(* Logix 5000 project; controller R21 vendor 1 type 14 code 96 rev 21.11; software revision 21.00; part 4 of 5 *)

ADD_ON_INSTRUCTION PSDNP3EventG30V03   (* revision 1.0, vendor ProSoft Technology Inc *)
VAR_IN_OUT
   EventBuffer : PSDNP3MasterEvent[1]; {required}
END_VAR
VAR_INPUT
   BufferSize : DINT; {required}
   CurrentBufferIndex : DINT; {required}
   Reset : BOOL; {required}
   OutstationNodeAddress : INT; {required}
   OutstationIPAddress0 : INT; {required}
   OutstationIPAddress1 : INT; {required}
   OutstationIPAddress2 : INT; {required}
   OutstationIPAddress3 : INT; {required}
END_VAR
VAR_IN_OUT
   DNP3StaticObject : DINT[1]; {required}
END_VAR
VAR_INPUT
   MaxtElementCount : DINT; {required}
END_VAR
VAR_OUTPUT
   EventsProcessed : DINT; {access Read Only, visible}
   LastElementIndex : DINT; {access Read Only, visible}
   LastValue : DINT; {access Read Only, visible}
   LastStatus : SINT; {access Read Only, visible}
   CurrentUnloadIndex : DINT; {access Read Only, visible}
END_VAR
VAR
   UnloadIndex : DINT; {access None}
   EnableInTemp : BOOL; {access None}
   InitialScan : BOOL; {access None}
   EntryValidForProcessing : BOOL; {access None}
   ElementIndex : DINT; {access None}
   NextIndex : DINT; {access None}
   ResetPulse : BOOL; {access None}
   ResetONS : BOOL; {access None}
END_VAR

ROUTINE Logic   (* ladder *)
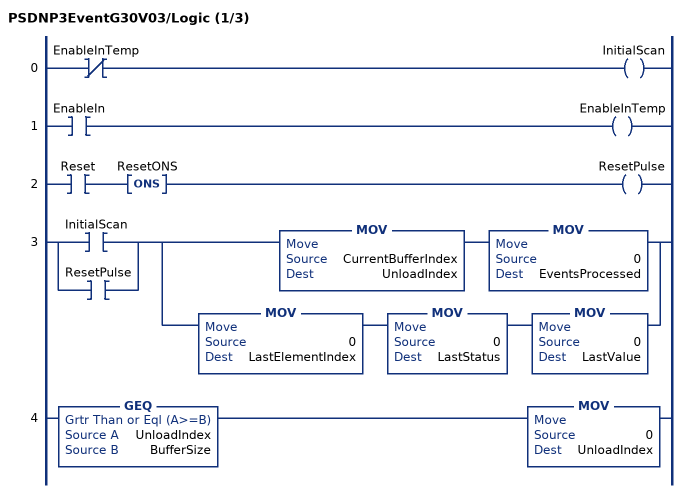
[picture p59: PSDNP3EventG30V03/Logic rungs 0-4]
   0: XIO(EnableInTemp)OTE(InitialScan);
   1: XIC(EnableIn)OTE(EnableInTemp);
   2: XIC(Reset)ONS(ResetONS)OTE(ResetPulse);
   3: [XIC(InitialScan) ,XIC(ResetPulse) ][MOV(CurrentBufferIndex,UnloadIndex) MOV(0,EventsProcessed) ,MOV(0,LastElementIndex) MOV(0,LastStatus) MOV(0,LastValue) ];
   4: GEQ(UnloadIndex,BufferSize)MOV(0,UnloadIndex);
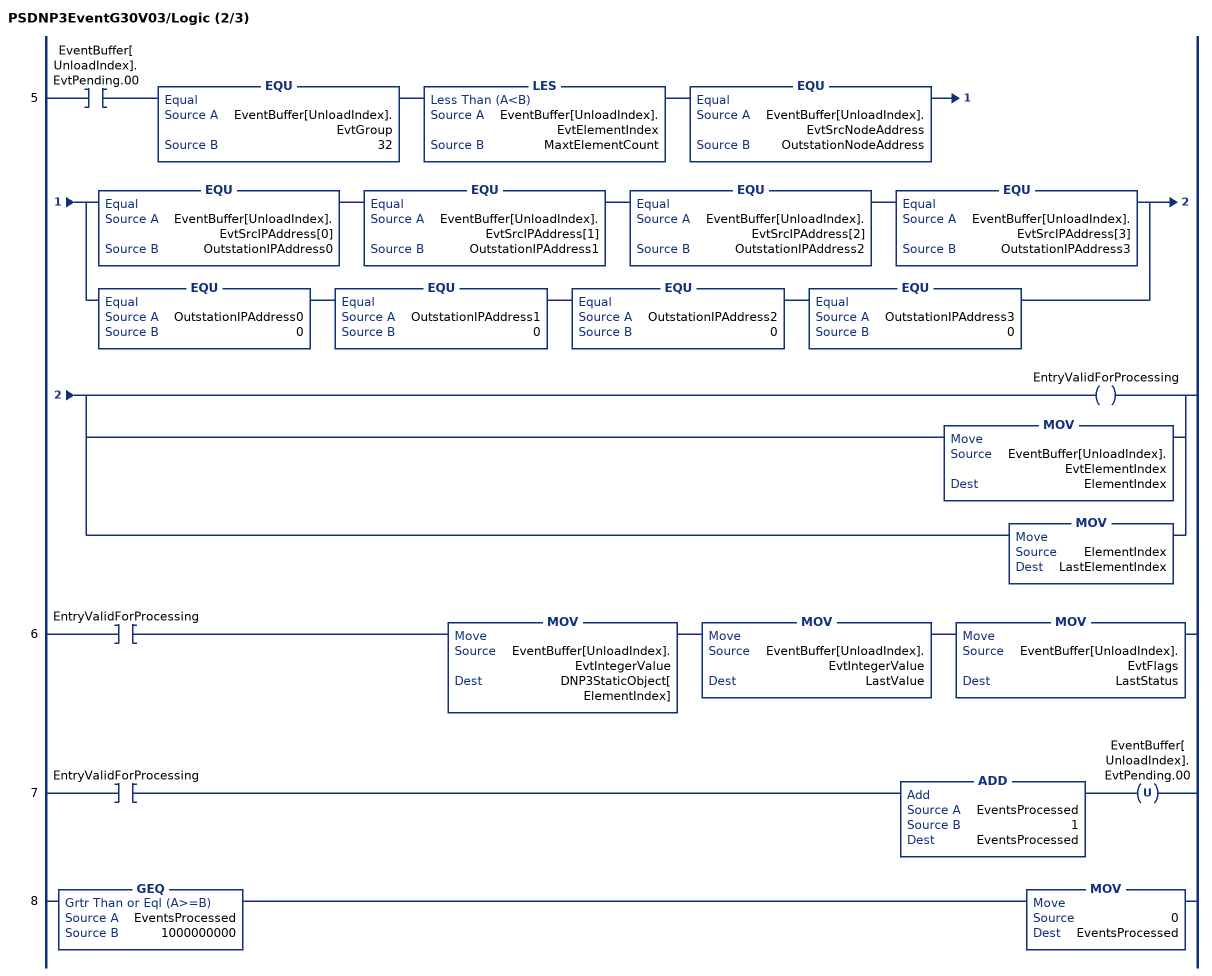
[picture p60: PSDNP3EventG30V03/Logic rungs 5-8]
   5: XIC(EventBuffer[UnloadIndex].EvtPending.00)EQU(EventBuffer[UnloadIndex].EvtGroup,32)LES(EventBuffer[UnloadIndex].EvtElementIndex,MaxtElementCount)EQU(EventBuffer[UnloadIndex].EvtSrcNodeAddress,OutstationNodeAddress)[EQU(EventBuffer[UnloadIndex].EvtSrcIPAddress[0],OutstationIPAddress0) EQU(EventBuffer[UnloadIndex].EvtSrcIPAddress[1],OutstationIPAddress1) EQU(EventBuffer[UnloadIndex].EvtSrcIPAddress[2],OutstationIPAddress2) EQU(EventBuffer[UnloadIndex].EvtSrcIPAddress[3],OutstationIPAddress3) ,EQU(OutstationIPAddress0,0) EQU(OutstationIPAddress1,0) EQU(OutstationIPAddress2,0) EQU(OutstationIPAddress3,0) ][OTE(EntryValidForProcessing) ,MOV(EventBuffer[UnloadIndex].EvtElementIndex,ElementIndex) ,MOV(ElementIndex,LastElementIndex) ];
   6: XIC(EntryValidForProcessing)MOV(EventBuffer[UnloadIndex].EvtIntegerValue,DNP3StaticObject[ElementIndex])MOV(EventBuffer[UnloadIndex].EvtIntegerValue,LastValue)MOV(EventBuffer[UnloadIndex].EvtFlags,LastStatus);
   7: XIC(EntryValidForProcessing)ADD(EventsProcessed,1,EventsProcessed)OTU(EventBuffer[UnloadIndex].EvtPending.00);
   8: GEQ(EventsProcessed,1000000000)MOV(0,EventsProcessed);
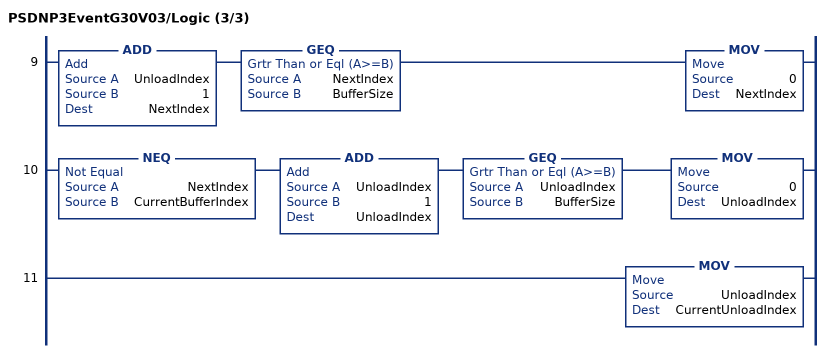
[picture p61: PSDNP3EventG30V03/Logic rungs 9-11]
   9: ADD(UnloadIndex,1,NextIndex)GEQ(NextIndex,BufferSize)MOV(0,NextIndex);
   10: NEQ(NextIndex,CurrentBufferIndex)ADD(UnloadIndex,1,UnloadIndex)GEQ(UnloadIndex,BufferSize)MOV(0,UnloadIndex);
   11: MOV(UnloadIndex,CurrentUnloadIndex);
END_ROUTINE
END_ADD_ON_INSTRUCTION

ADD_ON_INSTRUCTION PSDNP3EventG30V04   (* revision 1.0, vendor ProSoft Technology Inc *)
VAR_IN_OUT
   EventBuffer : PSDNP3MasterEvent[1]; {required}
END_VAR
VAR_INPUT
   BufferSize : DINT; {required}
   CurrentBufferIndex : DINT; {required}
   Reset : BOOL; {required}
   OutstationNodeAddress : INT; {required}
   OutstationIPAddress0 : INT; {required}
   OutstationIPAddress1 : INT; {required}
   OutstationIPAddress2 : INT; {required}
   OutstationIPAddress3 : INT; {required}
END_VAR
VAR_IN_OUT
   DNP3StaticObject : INT[1]; {required}
END_VAR
VAR_INPUT
   MaxtElementCount : DINT; {required}
END_VAR
VAR_OUTPUT
   EventsProcessed : DINT; {access Read Only, visible}
   LastElementIndex : DINT; {access Read Only, visible}
   LastValue : DINT; {access Read Only, visible}
   LastStatus : SINT; {access Read Only, visible}
   CurrentUnloadIndex : DINT; {access Read Only, visible}
END_VAR
VAR
   UnloadIndex : DINT; {access None}
   EnableInTemp : BOOL; {access None}
   InitialScan : BOOL; {access None}
   EntryValidForProcessing : BOOL; {access None}
   ElementIndex : DINT; {access None}
   NextIndex : DINT; {access None}
   ResetPulse : BOOL; {access None}
   ResetONS : BOOL; {access None}
END_VAR

ROUTINE Logic   (* ladder *)
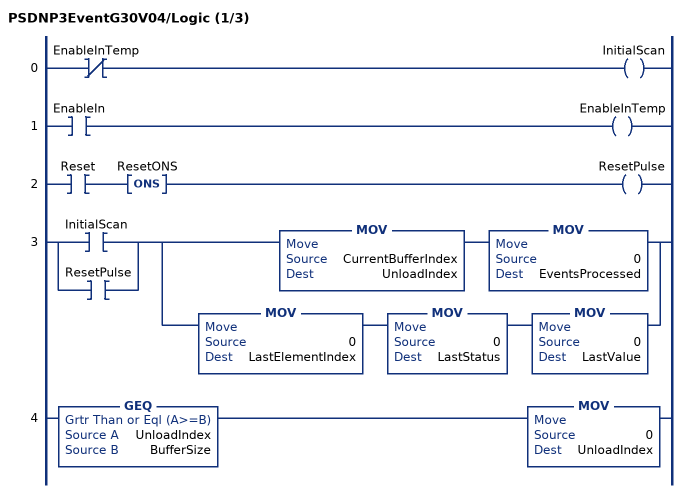
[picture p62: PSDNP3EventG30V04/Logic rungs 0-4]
   0: XIO(EnableInTemp)OTE(InitialScan);
   1: XIC(EnableIn)OTE(EnableInTemp);
   2: XIC(Reset)ONS(ResetONS)OTE(ResetPulse);
   3: [XIC(InitialScan) ,XIC(ResetPulse) ][MOV(CurrentBufferIndex,UnloadIndex) MOV(0,EventsProcessed) ,MOV(0,LastElementIndex) MOV(0,LastStatus) MOV(0,LastValue) ];
   4: GEQ(UnloadIndex,BufferSize)MOV(0,UnloadIndex);
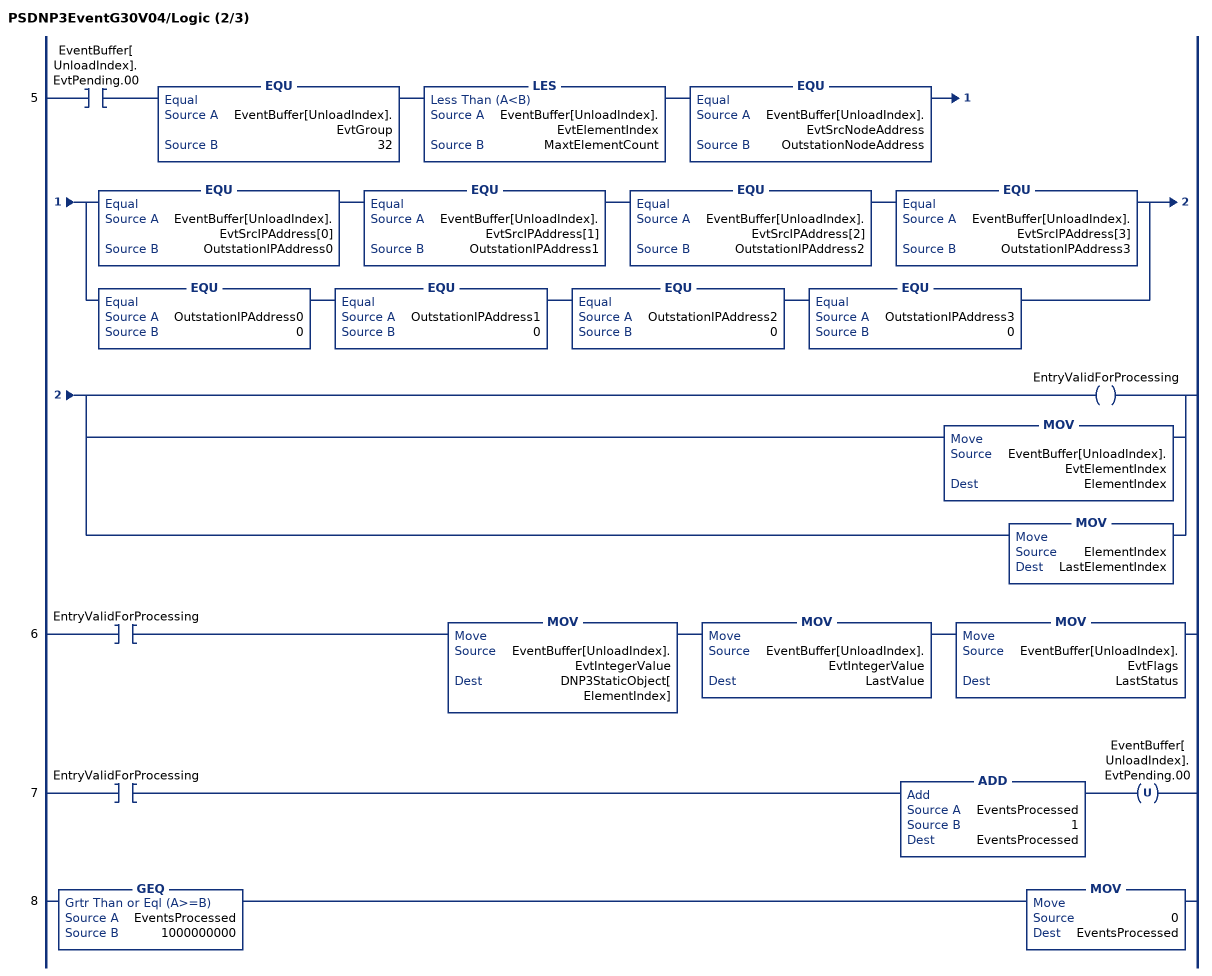
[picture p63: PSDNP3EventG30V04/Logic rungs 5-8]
   5: XIC(EventBuffer[UnloadIndex].EvtPending.00)EQU(EventBuffer[UnloadIndex].EvtGroup,32)LES(EventBuffer[UnloadIndex].EvtElementIndex,MaxtElementCount)EQU(EventBuffer[UnloadIndex].EvtSrcNodeAddress,OutstationNodeAddress)[EQU(EventBuffer[UnloadIndex].EvtSrcIPAddress[0],OutstationIPAddress0) EQU(EventBuffer[UnloadIndex].EvtSrcIPAddress[1],OutstationIPAddress1) EQU(EventBuffer[UnloadIndex].EvtSrcIPAddress[2],OutstationIPAddress2) EQU(EventBuffer[UnloadIndex].EvtSrcIPAddress[3],OutstationIPAddress3) ,EQU(OutstationIPAddress0,0) EQU(OutstationIPAddress1,0) EQU(OutstationIPAddress2,0) EQU(OutstationIPAddress3,0) ][OTE(EntryValidForProcessing) ,MOV(EventBuffer[UnloadIndex].EvtElementIndex,ElementIndex) ,MOV(ElementIndex,LastElementIndex) ];
   6: XIC(EntryValidForProcessing)MOV(EventBuffer[UnloadIndex].EvtIntegerValue,DNP3StaticObject[ElementIndex])MOV(EventBuffer[UnloadIndex].EvtIntegerValue,LastValue)MOV(EventBuffer[UnloadIndex].EvtFlags,LastStatus);
   7: XIC(EntryValidForProcessing)ADD(EventsProcessed,1,EventsProcessed)OTU(EventBuffer[UnloadIndex].EvtPending.00);
   8: GEQ(EventsProcessed,1000000000)MOV(0,EventsProcessed);
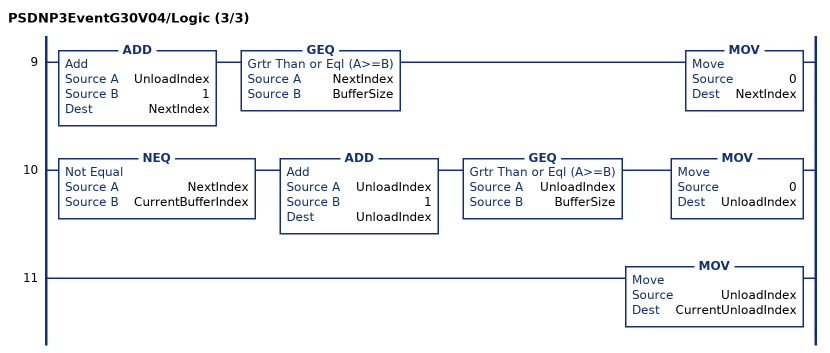
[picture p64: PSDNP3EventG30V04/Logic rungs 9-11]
   9: ADD(UnloadIndex,1,NextIndex)GEQ(NextIndex,BufferSize)MOV(0,NextIndex);
   10: NEQ(NextIndex,CurrentBufferIndex)ADD(UnloadIndex,1,UnloadIndex)GEQ(UnloadIndex,BufferSize)MOV(0,UnloadIndex);
   11: MOV(UnloadIndex,CurrentUnloadIndex);
END_ROUTINE
END_ADD_ON_INSTRUCTION

ADD_ON_INSTRUCTION PSDNP3EventG30V05   (* revision 1.0, vendor ProSoft Technology Inc *)
VAR_IN_OUT
   EventBuffer : PSDNP3MasterEvent[1]; {required}
END_VAR
VAR_INPUT
   BufferSize : DINT; {required}
   CurrentBufferIndex : DINT; {required}
   Reset : BOOL; {required}
   OutstationNodeAddress : INT; {required}
   OutstationIPAddress0 : INT; {required}
   OutstationIPAddress1 : INT; {required}
   OutstationIPAddress2 : INT; {required}
   OutstationIPAddress3 : INT; {required}
END_VAR
VAR_IN_OUT
   DNP3StaticObject : PSDNP3AnalogInputRealFlag[1]; {required}
END_VAR
VAR_INPUT
   MaxtElementCount : DINT; {required}
END_VAR
VAR_OUTPUT
   EventsProcessed : DINT; {access Read Only, visible}
   LastElementIndex : DINT; {access Read Only, visible}
   LastValue : REAL; {access Read Only, visible}
   LastStatus : SINT; {access Read Only, visible}
   CurrentUnloadIndex : DINT; {access Read Only, visible}
END_VAR
VAR
   UnloadIndex : DINT; {access None}
   EnableInTemp : BOOL; {access None}
   InitialScan : BOOL; {access None}
   EntryValidForProcessing : BOOL; {access None}
   ElementIndex : DINT; {access None}
   NextIndex : DINT; {access None}
   ResetPulse : BOOL; {access None}
   ResetONS : BOOL; {access None}
END_VAR

ROUTINE Logic   (* ladder *)
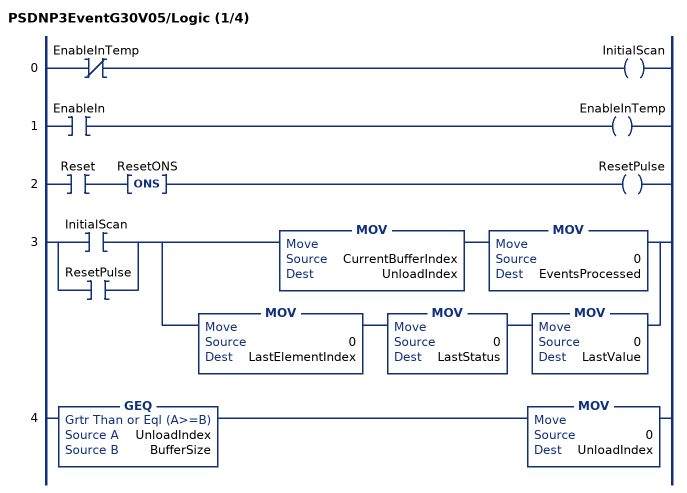
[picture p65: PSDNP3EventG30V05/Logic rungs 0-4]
   0: XIO(EnableInTemp)OTE(InitialScan);
   1: XIC(EnableIn)OTE(EnableInTemp);
   2: XIC(Reset)ONS(ResetONS)OTE(ResetPulse);
   3: [XIC(InitialScan) ,XIC(ResetPulse) ][MOV(CurrentBufferIndex,UnloadIndex) MOV(0,EventsProcessed) ,MOV(0,LastElementIndex) MOV(0,LastStatus) MOV(0,LastValue) ];
   4: GEQ(UnloadIndex,BufferSize)MOV(0,UnloadIndex);
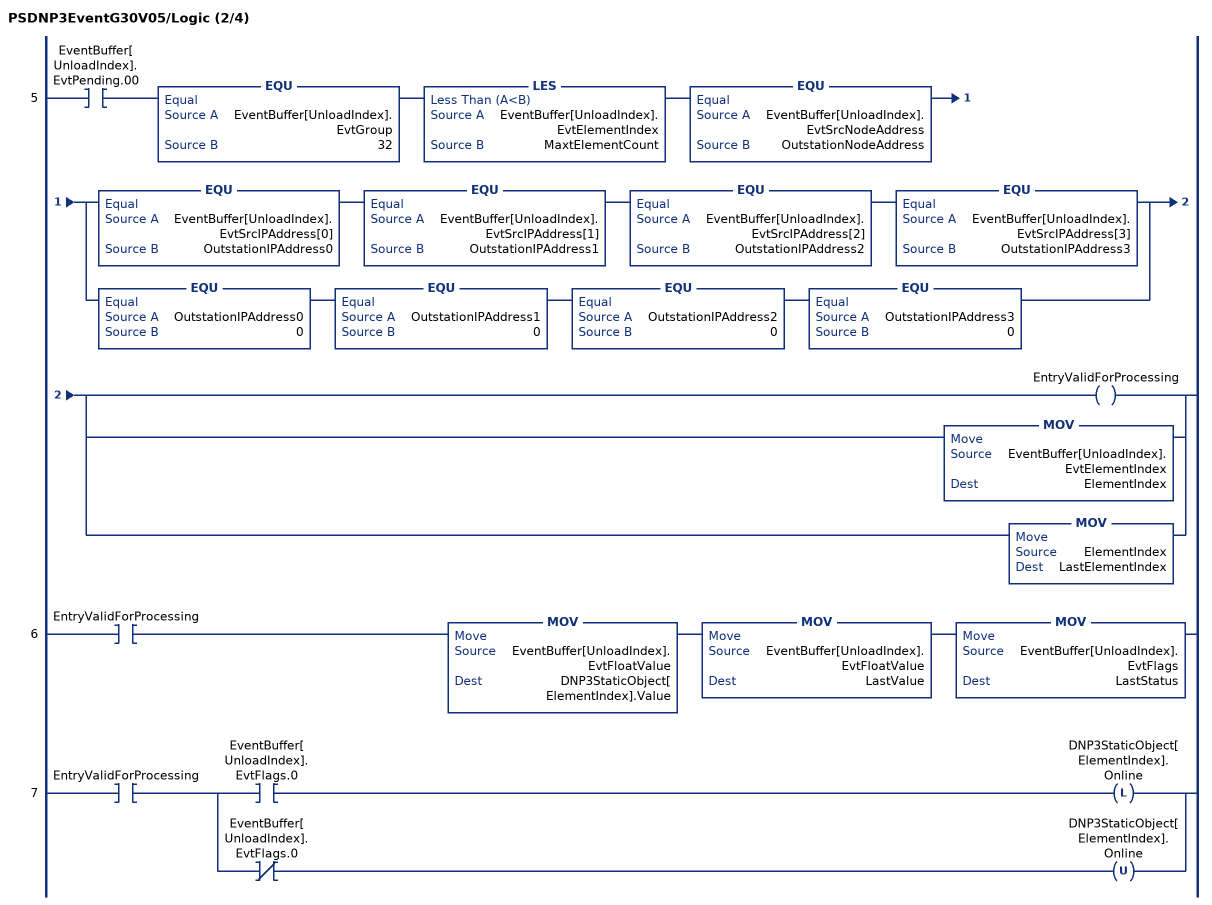
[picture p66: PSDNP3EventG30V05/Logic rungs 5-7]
   5: XIC(EventBuffer[UnloadIndex].EvtPending.00)EQU(EventBuffer[UnloadIndex].EvtGroup,32)LES(EventBuffer[UnloadIndex].EvtElementIndex,MaxtElementCount)EQU(EventBuffer[UnloadIndex].EvtSrcNodeAddress,OutstationNodeAddress)[EQU(EventBuffer[UnloadIndex].EvtSrcIPAddress[0],OutstationIPAddress0) EQU(EventBuffer[UnloadIndex].EvtSrcIPAddress[1],OutstationIPAddress1) EQU(EventBuffer[UnloadIndex].EvtSrcIPAddress[2],OutstationIPAddress2) EQU(EventBuffer[UnloadIndex].EvtSrcIPAddress[3],OutstationIPAddress3) ,EQU(OutstationIPAddress0,0) EQU(OutstationIPAddress1,0) EQU(OutstationIPAddress2,0) EQU(OutstationIPAddress3,0) ][OTE(EntryValidForProcessing) ,MOV(EventBuffer[UnloadIndex].EvtElementIndex,ElementIndex) ,MOV(ElementIndex,LastElementIndex) ];
   6: XIC(EntryValidForProcessing)MOV(EventBuffer[UnloadIndex].EvtFloatValue,DNP3StaticObject[ElementIndex].Value)MOV(EventBuffer[UnloadIndex].EvtFloatValue,LastValue)MOV(EventBuffer[UnloadIndex].EvtFlags,LastStatus);
   7: XIC(EntryValidForProcessing)[XIC(EventBuffer[UnloadIndex].EvtFlags.0) OTL(DNP3StaticObject[ElementIndex].Online) ,XIO(EventBuffer[UnloadIndex].EvtFlags.0) OTU(DNP3StaticObject[ElementIndex].Online) ];
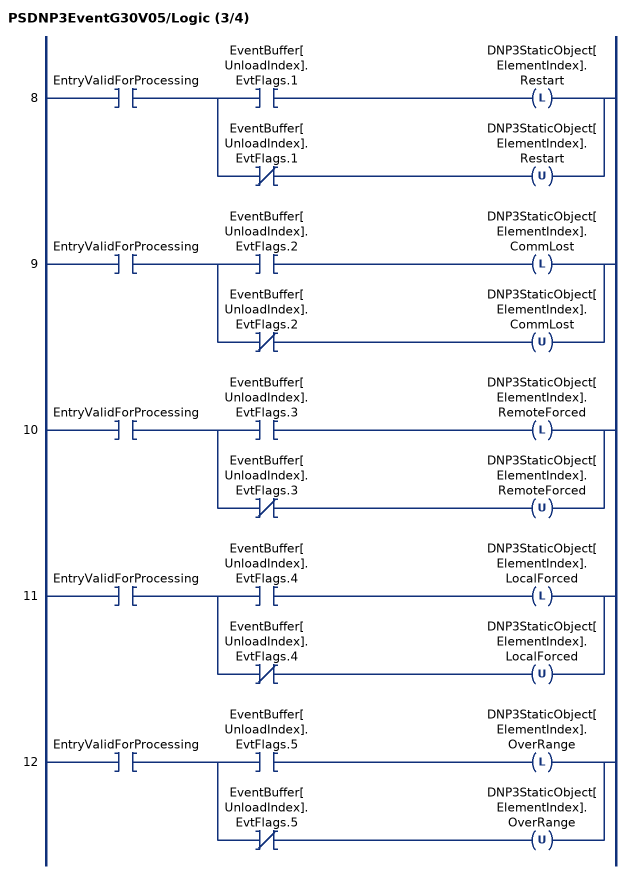
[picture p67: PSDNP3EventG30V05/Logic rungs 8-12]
   8: XIC(EntryValidForProcessing)[XIC(EventBuffer[UnloadIndex].EvtFlags.1) OTL(DNP3StaticObject[ElementIndex].Restart) ,XIO(EventBuffer[UnloadIndex].EvtFlags.1) OTU(DNP3StaticObject[ElementIndex].Restart) ];
   9: XIC(EntryValidForProcessing)[XIC(EventBuffer[UnloadIndex].EvtFlags.2) OTL(DNP3StaticObject[ElementIndex].CommLost) ,XIO(EventBuffer[UnloadIndex].EvtFlags.2) OTU(DNP3StaticObject[ElementIndex].CommLost) ];
   10: XIC(EntryValidForProcessing)[XIC(EventBuffer[UnloadIndex].EvtFlags.3) OTL(DNP3StaticObject[ElementIndex].RemoteForced) ,XIO(EventBuffer[UnloadIndex].EvtFlags.3) OTU(DNP3StaticObject[ElementIndex].RemoteForced) ];
   11: XIC(EntryValidForProcessing)[XIC(EventBuffer[UnloadIndex].EvtFlags.4) OTL(DNP3StaticObject[ElementIndex].LocalForced) ,XIO(EventBuffer[UnloadIndex].EvtFlags.4) OTU(DNP3StaticObject[ElementIndex].LocalForced) ];
   12: XIC(EntryValidForProcessing)[XIC(EventBuffer[UnloadIndex].EvtFlags.5) OTL(DNP3StaticObject[ElementIndex].OverRange) ,XIO(EventBuffer[UnloadIndex].EvtFlags.5) OTU(DNP3StaticObject[ElementIndex].OverRange) ];
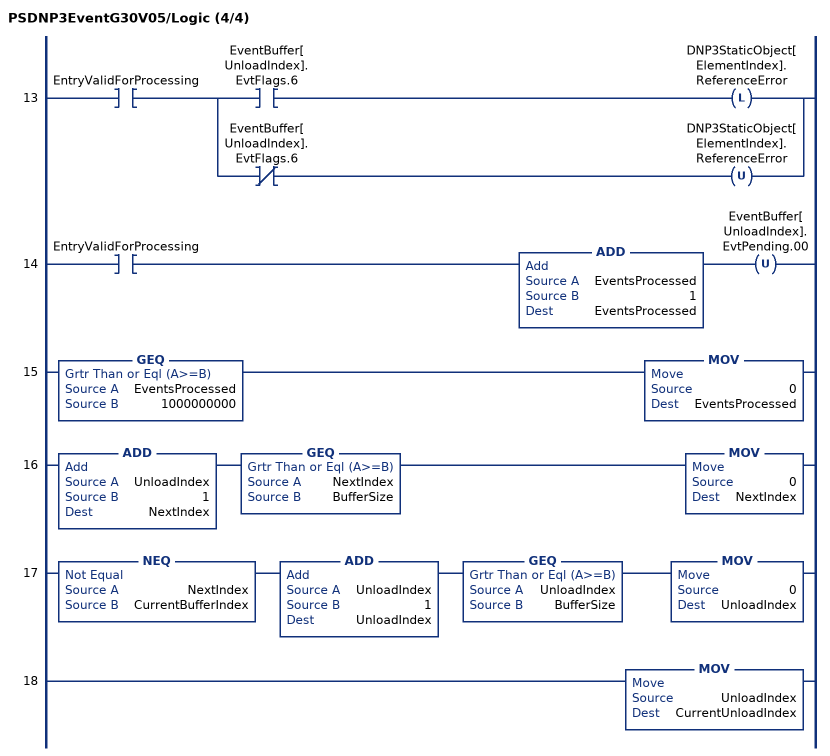
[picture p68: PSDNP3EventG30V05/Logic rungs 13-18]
   13: XIC(EntryValidForProcessing)[XIC(EventBuffer[UnloadIndex].EvtFlags.6) OTL(DNP3StaticObject[ElementIndex].ReferenceError) ,XIO(EventBuffer[UnloadIndex].EvtFlags.6) OTU(DNP3StaticObject[ElementIndex].ReferenceError) ];
   14: XIC(EntryValidForProcessing)ADD(EventsProcessed,1,EventsProcessed)OTU(EventBuffer[UnloadIndex].EvtPending.00);
   15: GEQ(EventsProcessed,1000000000)MOV(0,EventsProcessed);
   16: ADD(UnloadIndex,1,NextIndex)GEQ(NextIndex,BufferSize)MOV(0,NextIndex);
   17: NEQ(NextIndex,CurrentBufferIndex)ADD(UnloadIndex,1,UnloadIndex)GEQ(UnloadIndex,BufferSize)MOV(0,UnloadIndex);
   18: MOV(UnloadIndex,CurrentUnloadIndex);
END_ROUTINE
END_ADD_ON_INSTRUCTION

ADD_ON_INSTRUCTION PSDNP3EventG40V01   (* revision 1.0, vendor ProSoft Technology Inc *)
VAR_IN_OUT
   EventBuffer : PSDNP3MasterEvent[1]; {required}
END_VAR
VAR_INPUT
   BufferSize : DINT; {required}
   CurrentBufferIndex : DINT; {required}
   Reset : BOOL; {required}
   OutstationNodeAddress : INT; {required}
   OutstationIPAddress0 : INT; {required}
   OutstationIPAddress1 : INT; {required}
   OutstationIPAddress2 : INT; {required}
   OutstationIPAddress3 : INT; {required}
END_VAR
VAR_IN_OUT
   DNP3StaticObject : PSDNP3AnalogOutputStatus32Flag[1]; {required}
END_VAR
VAR_INPUT
   MaxtElementCount : DINT; {required}
END_VAR
VAR_OUTPUT
   EventsProcessed : DINT; {access Read Only, visible}
   LastElementIndex : DINT; {access Read Only, visible}
   LastValue : DINT; {access Read Only, visible}
   LastStatus : SINT; {access Read Only, visible}
   CurrentUnloadIndex : DINT; {access Read Only, visible}
END_VAR
VAR
   UnloadIndex : DINT; {access None}
   EnableInTemp : BOOL; {access None}
   InitialScan : BOOL; {access None}
   EntryValidForProcessing : BOOL; {access None}
   ElementIndex : DINT; {access None}
   NextIndex : DINT; {access None}
   ResetPulse : BOOL; {access None}
   ResetONS : BOOL; {access None}
END_VAR

ROUTINE Logic   (* ladder *)
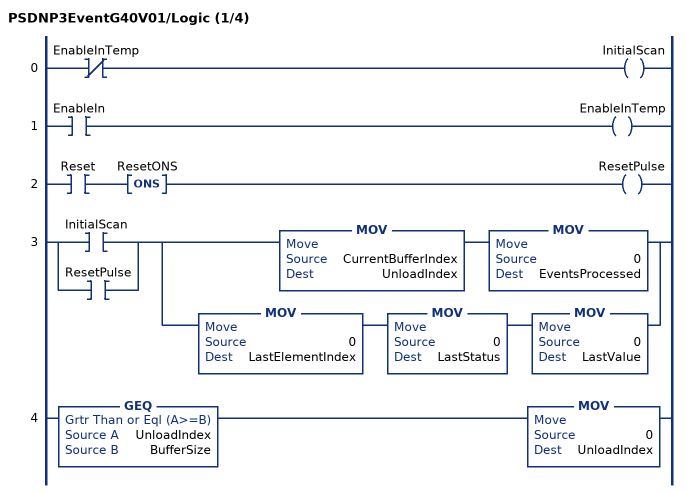
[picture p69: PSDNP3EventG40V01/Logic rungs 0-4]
   0: XIO(EnableInTemp)OTE(InitialScan);
   1: XIC(EnableIn)OTE(EnableInTemp);
   2: XIC(Reset)ONS(ResetONS)OTE(ResetPulse);
   3: [XIC(InitialScan) ,XIC(ResetPulse) ][MOV(CurrentBufferIndex,UnloadIndex) MOV(0,EventsProcessed) ,MOV(0,LastElementIndex) MOV(0,LastStatus) MOV(0,LastValue) ];
   4: GEQ(UnloadIndex,BufferSize)MOV(0,UnloadIndex);
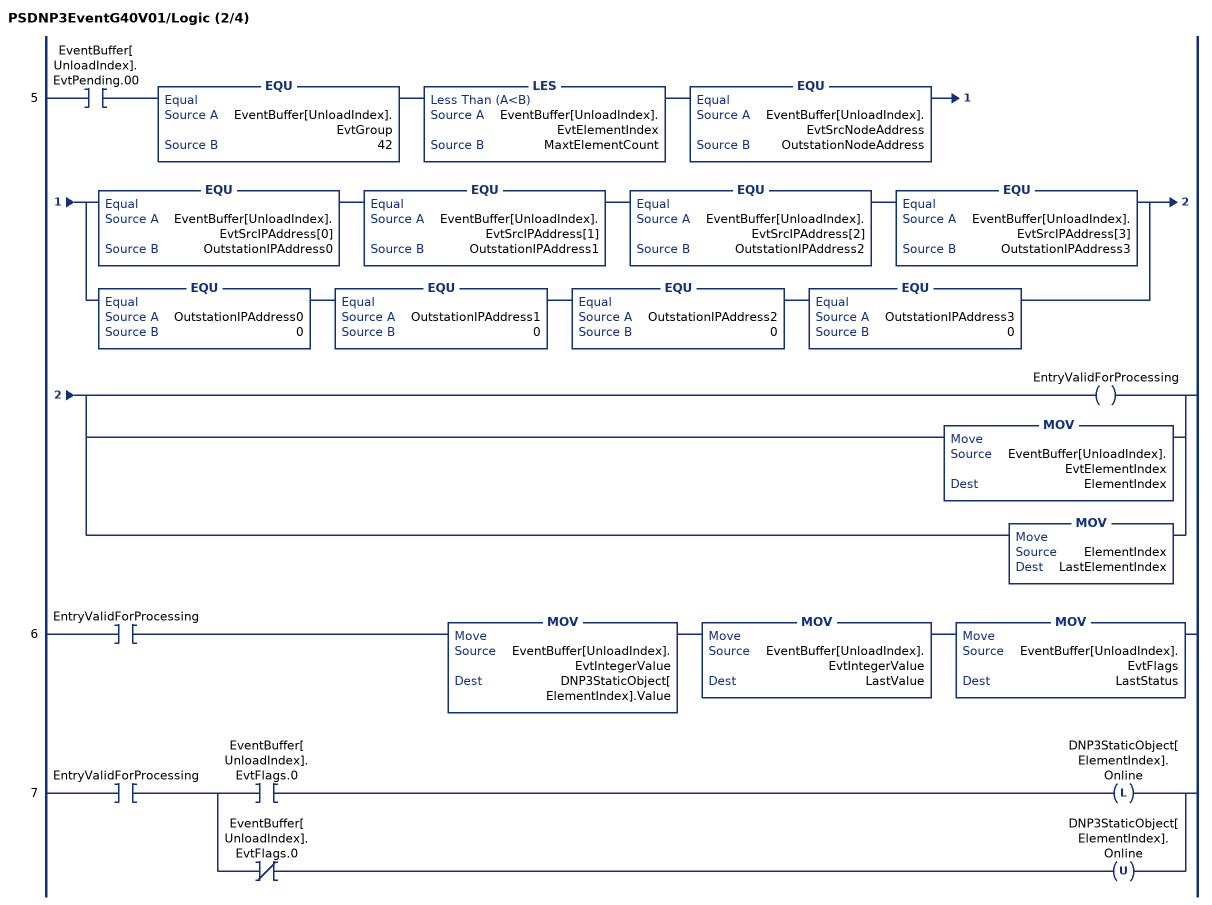
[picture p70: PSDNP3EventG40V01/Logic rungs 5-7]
   5: XIC(EventBuffer[UnloadIndex].EvtPending.00)EQU(EventBuffer[UnloadIndex].EvtGroup,42)LES(EventBuffer[UnloadIndex].EvtElementIndex,MaxtElementCount)EQU(EventBuffer[UnloadIndex].EvtSrcNodeAddress,OutstationNodeAddress)[EQU(EventBuffer[UnloadIndex].EvtSrcIPAddress[0],OutstationIPAddress0) EQU(EventBuffer[UnloadIndex].EvtSrcIPAddress[1],OutstationIPAddress1) EQU(EventBuffer[UnloadIndex].EvtSrcIPAddress[2],OutstationIPAddress2) EQU(EventBuffer[UnloadIndex].EvtSrcIPAddress[3],OutstationIPAddress3) ,EQU(OutstationIPAddress0,0) EQU(OutstationIPAddress1,0) EQU(OutstationIPAddress2,0) EQU(OutstationIPAddress3,0) ][OTE(EntryValidForProcessing) ,MOV(EventBuffer[UnloadIndex].EvtElementIndex,ElementIndex) ,MOV(ElementIndex,LastElementIndex) ];
   6: XIC(EntryValidForProcessing)MOV(EventBuffer[UnloadIndex].EvtIntegerValue,DNP3StaticObject[ElementIndex].Value)MOV(EventBuffer[UnloadIndex].EvtIntegerValue,LastValue)MOV(EventBuffer[UnloadIndex].EvtFlags,LastStatus);
   7: XIC(EntryValidForProcessing)[XIC(EventBuffer[UnloadIndex].EvtFlags.0) OTL(DNP3StaticObject[ElementIndex].Online) ,XIO(EventBuffer[UnloadIndex].EvtFlags.0) OTU(DNP3StaticObject[ElementIndex].Online) ];
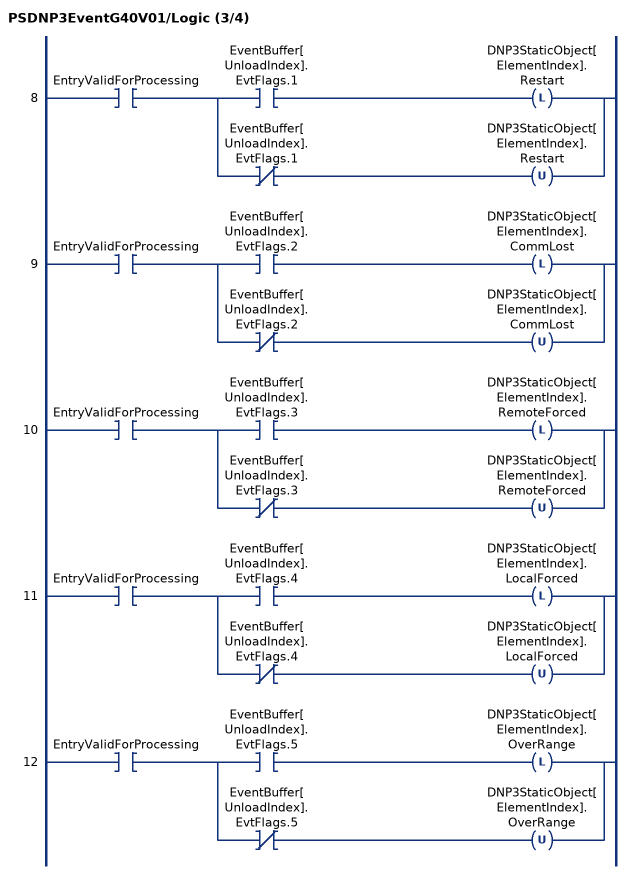
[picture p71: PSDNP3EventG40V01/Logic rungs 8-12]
   8: XIC(EntryValidForProcessing)[XIC(EventBuffer[UnloadIndex].EvtFlags.1) OTL(DNP3StaticObject[ElementIndex].Restart) ,XIO(EventBuffer[UnloadIndex].EvtFlags.1) OTU(DNP3StaticObject[ElementIndex].Restart) ];
   9: XIC(EntryValidForProcessing)[XIC(EventBuffer[UnloadIndex].EvtFlags.2) OTL(DNP3StaticObject[ElementIndex].CommLost) ,XIO(EventBuffer[UnloadIndex].EvtFlags.2) OTU(DNP3StaticObject[ElementIndex].CommLost) ];
   10: XIC(EntryValidForProcessing)[XIC(EventBuffer[UnloadIndex].EvtFlags.3) OTL(DNP3StaticObject[ElementIndex].RemoteForced) ,XIO(EventBuffer[UnloadIndex].EvtFlags.3) OTU(DNP3StaticObject[ElementIndex].RemoteForced) ];
   11: XIC(EntryValidForProcessing)[XIC(EventBuffer[UnloadIndex].EvtFlags.4) OTL(DNP3StaticObject[ElementIndex].LocalForced) ,XIO(EventBuffer[UnloadIndex].EvtFlags.4) OTU(DNP3StaticObject[ElementIndex].LocalForced) ];
   12: XIC(EntryValidForProcessing)[XIC(EventBuffer[UnloadIndex].EvtFlags.5) OTL(DNP3StaticObject[ElementIndex].OverRange) ,XIO(EventBuffer[UnloadIndex].EvtFlags.5) OTU(DNP3StaticObject[ElementIndex].OverRange) ];
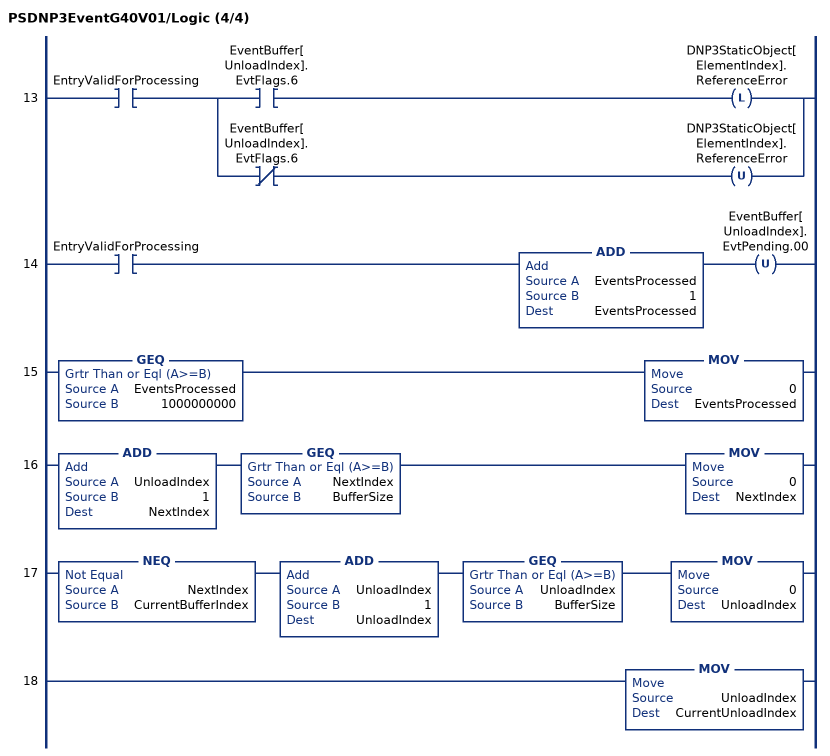
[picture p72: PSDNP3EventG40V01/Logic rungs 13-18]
   13: XIC(EntryValidForProcessing)[XIC(EventBuffer[UnloadIndex].EvtFlags.6) OTL(DNP3StaticObject[ElementIndex].ReferenceError) ,XIO(EventBuffer[UnloadIndex].EvtFlags.6) OTU(DNP3StaticObject[ElementIndex].ReferenceError) ];
   14: XIC(EntryValidForProcessing)ADD(EventsProcessed,1,EventsProcessed)OTU(EventBuffer[UnloadIndex].EvtPending.00);
   15: GEQ(EventsProcessed,1000000000)MOV(0,EventsProcessed);
   16: ADD(UnloadIndex,1,NextIndex)GEQ(NextIndex,BufferSize)MOV(0,NextIndex);
   17: NEQ(NextIndex,CurrentBufferIndex)ADD(UnloadIndex,1,UnloadIndex)GEQ(UnloadIndex,BufferSize)MOV(0,UnloadIndex);
   18: MOV(UnloadIndex,CurrentUnloadIndex);
END_ROUTINE
END_ADD_ON_INSTRUCTION

ADD_ON_INSTRUCTION PSDNP3EventG40V02   (* revision 1.0, vendor ProSoft Technology Inc *)
VAR_IN_OUT
   EventBuffer : PSDNP3MasterEvent[1]; {required}
END_VAR
VAR_INPUT
   BufferSize : DINT; {required}
   CurrentBufferIndex : DINT; {required}
   Reset : BOOL; {required}
   OutstationNodeAddress : INT; {required}
   OutstationIPAddress0 : INT; {required}
   OutstationIPAddress1 : INT; {required}
   OutstationIPAddress2 : INT; {required}
   OutstationIPAddress3 : INT; {required}
END_VAR
VAR_IN_OUT
   DNP3StaticObject : PSDNP3AnalogOutputStatus16Flag[1]; {required}
END_VAR
VAR_INPUT
   MaxtElementCount : DINT; {required}
END_VAR
VAR_OUTPUT
   EventsProcessed : DINT; {access Read Only, visible}
   LastElementIndex : DINT; {access Read Only, visible}
   LastValue : DINT; {access Read Only, visible}
   LastStatus : SINT; {access Read Only, visible}
   CurrentUnloadIndex : DINT; {access Read Only, visible}
END_VAR
VAR
   UnloadIndex : DINT; {access None}
   EnableInTemp : BOOL; {access None}
   InitialScan : BOOL; {access None}
   EntryValidForProcessing : BOOL; {access None}
   ElementIndex : DINT; {access None}
   NextIndex : DINT; {access None}
   ResetPulse : BOOL; {access None}
   ResetONS : BOOL; {access None}
END_VAR

ROUTINE Logic   (* ladder *)
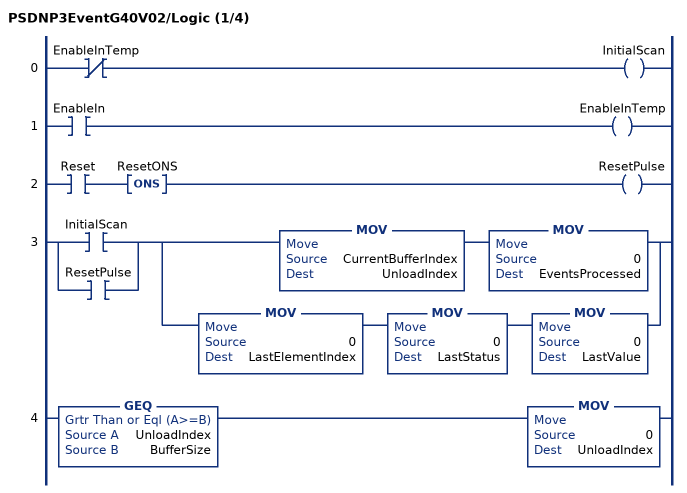
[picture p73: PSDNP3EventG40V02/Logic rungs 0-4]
   0: XIO(EnableInTemp)OTE(InitialScan);
   1: XIC(EnableIn)OTE(EnableInTemp);
   2: XIC(Reset)ONS(ResetONS)OTE(ResetPulse);
   3: [XIC(InitialScan) ,XIC(ResetPulse) ][MOV(CurrentBufferIndex,UnloadIndex) MOV(0,EventsProcessed) ,MOV(0,LastElementIndex) MOV(0,LastStatus) MOV(0,LastValue) ];
   4: GEQ(UnloadIndex,BufferSize)MOV(0,UnloadIndex);
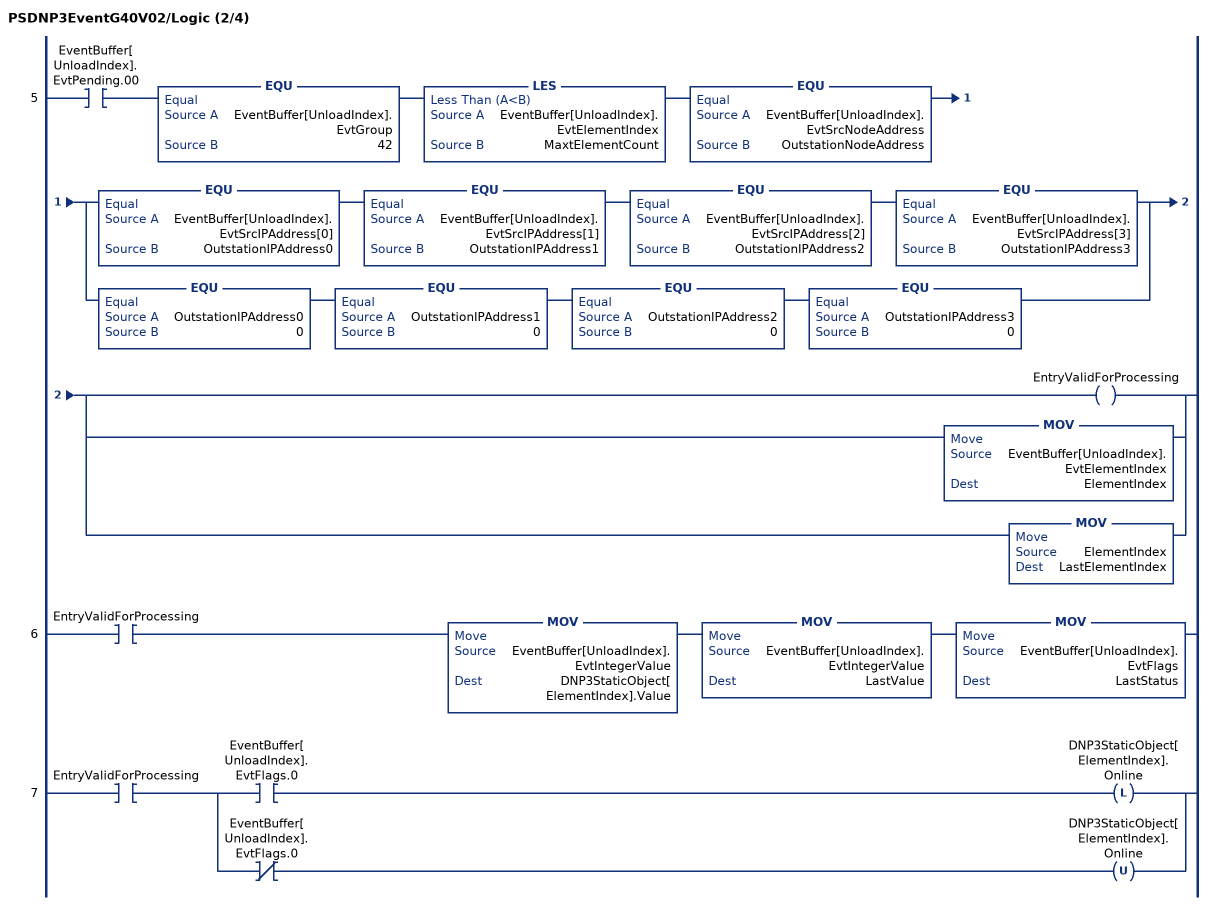
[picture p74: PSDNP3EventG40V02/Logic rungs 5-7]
   5: XIC(EventBuffer[UnloadIndex].EvtPending.00)EQU(EventBuffer[UnloadIndex].EvtGroup,42)LES(EventBuffer[UnloadIndex].EvtElementIndex,MaxtElementCount)EQU(EventBuffer[UnloadIndex].EvtSrcNodeAddress,OutstationNodeAddress)[EQU(EventBuffer[UnloadIndex].EvtSrcIPAddress[0],OutstationIPAddress0) EQU(EventBuffer[UnloadIndex].EvtSrcIPAddress[1],OutstationIPAddress1) EQU(EventBuffer[UnloadIndex].EvtSrcIPAddress[2],OutstationIPAddress2) EQU(EventBuffer[UnloadIndex].EvtSrcIPAddress[3],OutstationIPAddress3) ,EQU(OutstationIPAddress0,0) EQU(OutstationIPAddress1,0) EQU(OutstationIPAddress2,0) EQU(OutstationIPAddress3,0) ][OTE(EntryValidForProcessing) ,MOV(EventBuffer[UnloadIndex].EvtElementIndex,ElementIndex) ,MOV(ElementIndex,LastElementIndex) ];
   6: XIC(EntryValidForProcessing)MOV(EventBuffer[UnloadIndex].EvtIntegerValue,DNP3StaticObject[ElementIndex].Value)MOV(EventBuffer[UnloadIndex].EvtIntegerValue,LastValue)MOV(EventBuffer[UnloadIndex].EvtFlags,LastStatus);
   7: XIC(EntryValidForProcessing)[XIC(EventBuffer[UnloadIndex].EvtFlags.0) OTL(DNP3StaticObject[ElementIndex].Online) ,XIO(EventBuffer[UnloadIndex].EvtFlags.0) OTU(DNP3StaticObject[ElementIndex].Online) ];
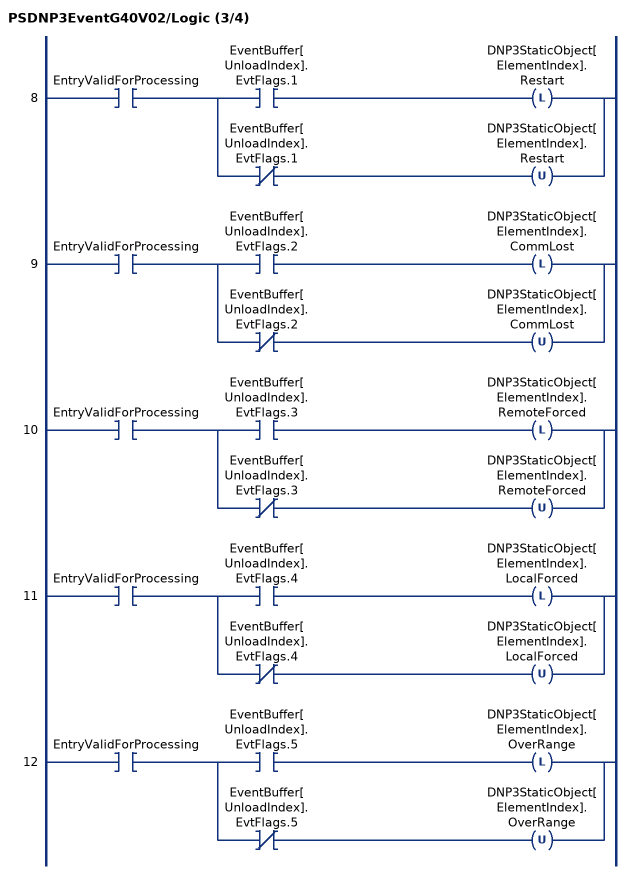
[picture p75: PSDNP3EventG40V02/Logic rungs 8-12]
   8: XIC(EntryValidForProcessing)[XIC(EventBuffer[UnloadIndex].EvtFlags.1) OTL(DNP3StaticObject[ElementIndex].Restart) ,XIO(EventBuffer[UnloadIndex].EvtFlags.1) OTU(DNP3StaticObject[ElementIndex].Restart) ];
   9: XIC(EntryValidForProcessing)[XIC(EventBuffer[UnloadIndex].EvtFlags.2) OTL(DNP3StaticObject[ElementIndex].CommLost) ,XIO(EventBuffer[UnloadIndex].EvtFlags.2) OTU(DNP3StaticObject[ElementIndex].CommLost) ];
   10: XIC(EntryValidForProcessing)[XIC(EventBuffer[UnloadIndex].EvtFlags.3) OTL(DNP3StaticObject[ElementIndex].RemoteForced) ,XIO(EventBuffer[UnloadIndex].EvtFlags.3) OTU(DNP3StaticObject[ElementIndex].RemoteForced) ];
   11: XIC(EntryValidForProcessing)[XIC(EventBuffer[UnloadIndex].EvtFlags.4) OTL(DNP3StaticObject[ElementIndex].LocalForced) ,XIO(EventBuffer[UnloadIndex].EvtFlags.4) OTU(DNP3StaticObject[ElementIndex].LocalForced) ];
   12: XIC(EntryValidForProcessing)[XIC(EventBuffer[UnloadIndex].EvtFlags.5) OTL(DNP3StaticObject[ElementIndex].OverRange) ,XIO(EventBuffer[UnloadIndex].EvtFlags.5) OTU(DNP3StaticObject[ElementIndex].OverRange) ];
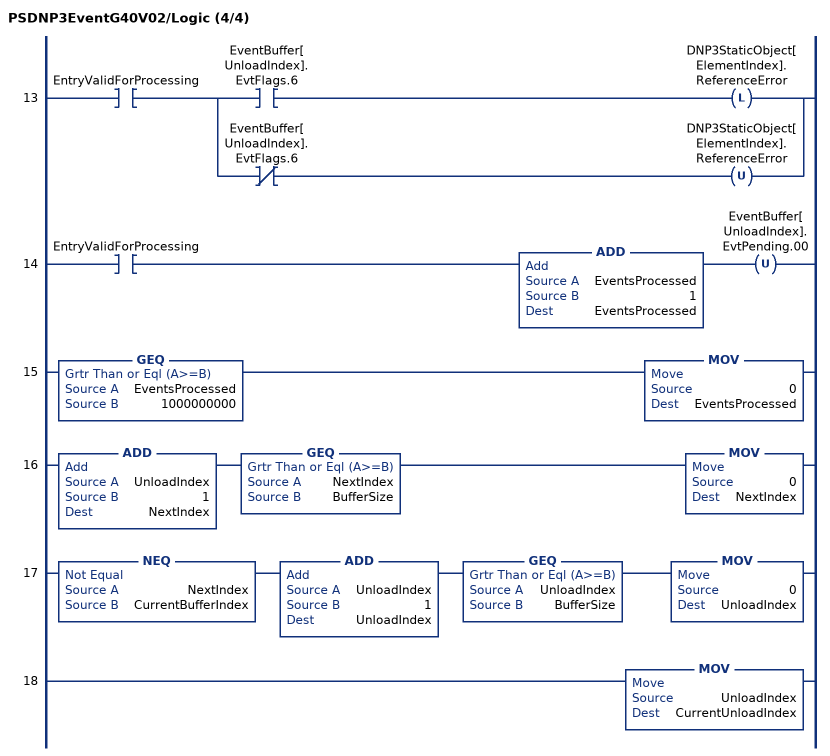
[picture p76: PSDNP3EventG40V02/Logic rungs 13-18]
   13: XIC(EntryValidForProcessing)[XIC(EventBuffer[UnloadIndex].EvtFlags.6) OTL(DNP3StaticObject[ElementIndex].ReferenceError) ,XIO(EventBuffer[UnloadIndex].EvtFlags.6) OTU(DNP3StaticObject[ElementIndex].ReferenceError) ];
   14: XIC(EntryValidForProcessing)ADD(EventsProcessed,1,EventsProcessed)OTU(EventBuffer[UnloadIndex].EvtPending.00);
   15: GEQ(EventsProcessed,1000000000)MOV(0,EventsProcessed);
   16: ADD(UnloadIndex,1,NextIndex)GEQ(NextIndex,BufferSize)MOV(0,NextIndex);
   17: NEQ(NextIndex,CurrentBufferIndex)ADD(UnloadIndex,1,UnloadIndex)GEQ(UnloadIndex,BufferSize)MOV(0,UnloadIndex);
   18: MOV(UnloadIndex,CurrentUnloadIndex);
END_ROUTINE
END_ADD_ON_INSTRUCTION
